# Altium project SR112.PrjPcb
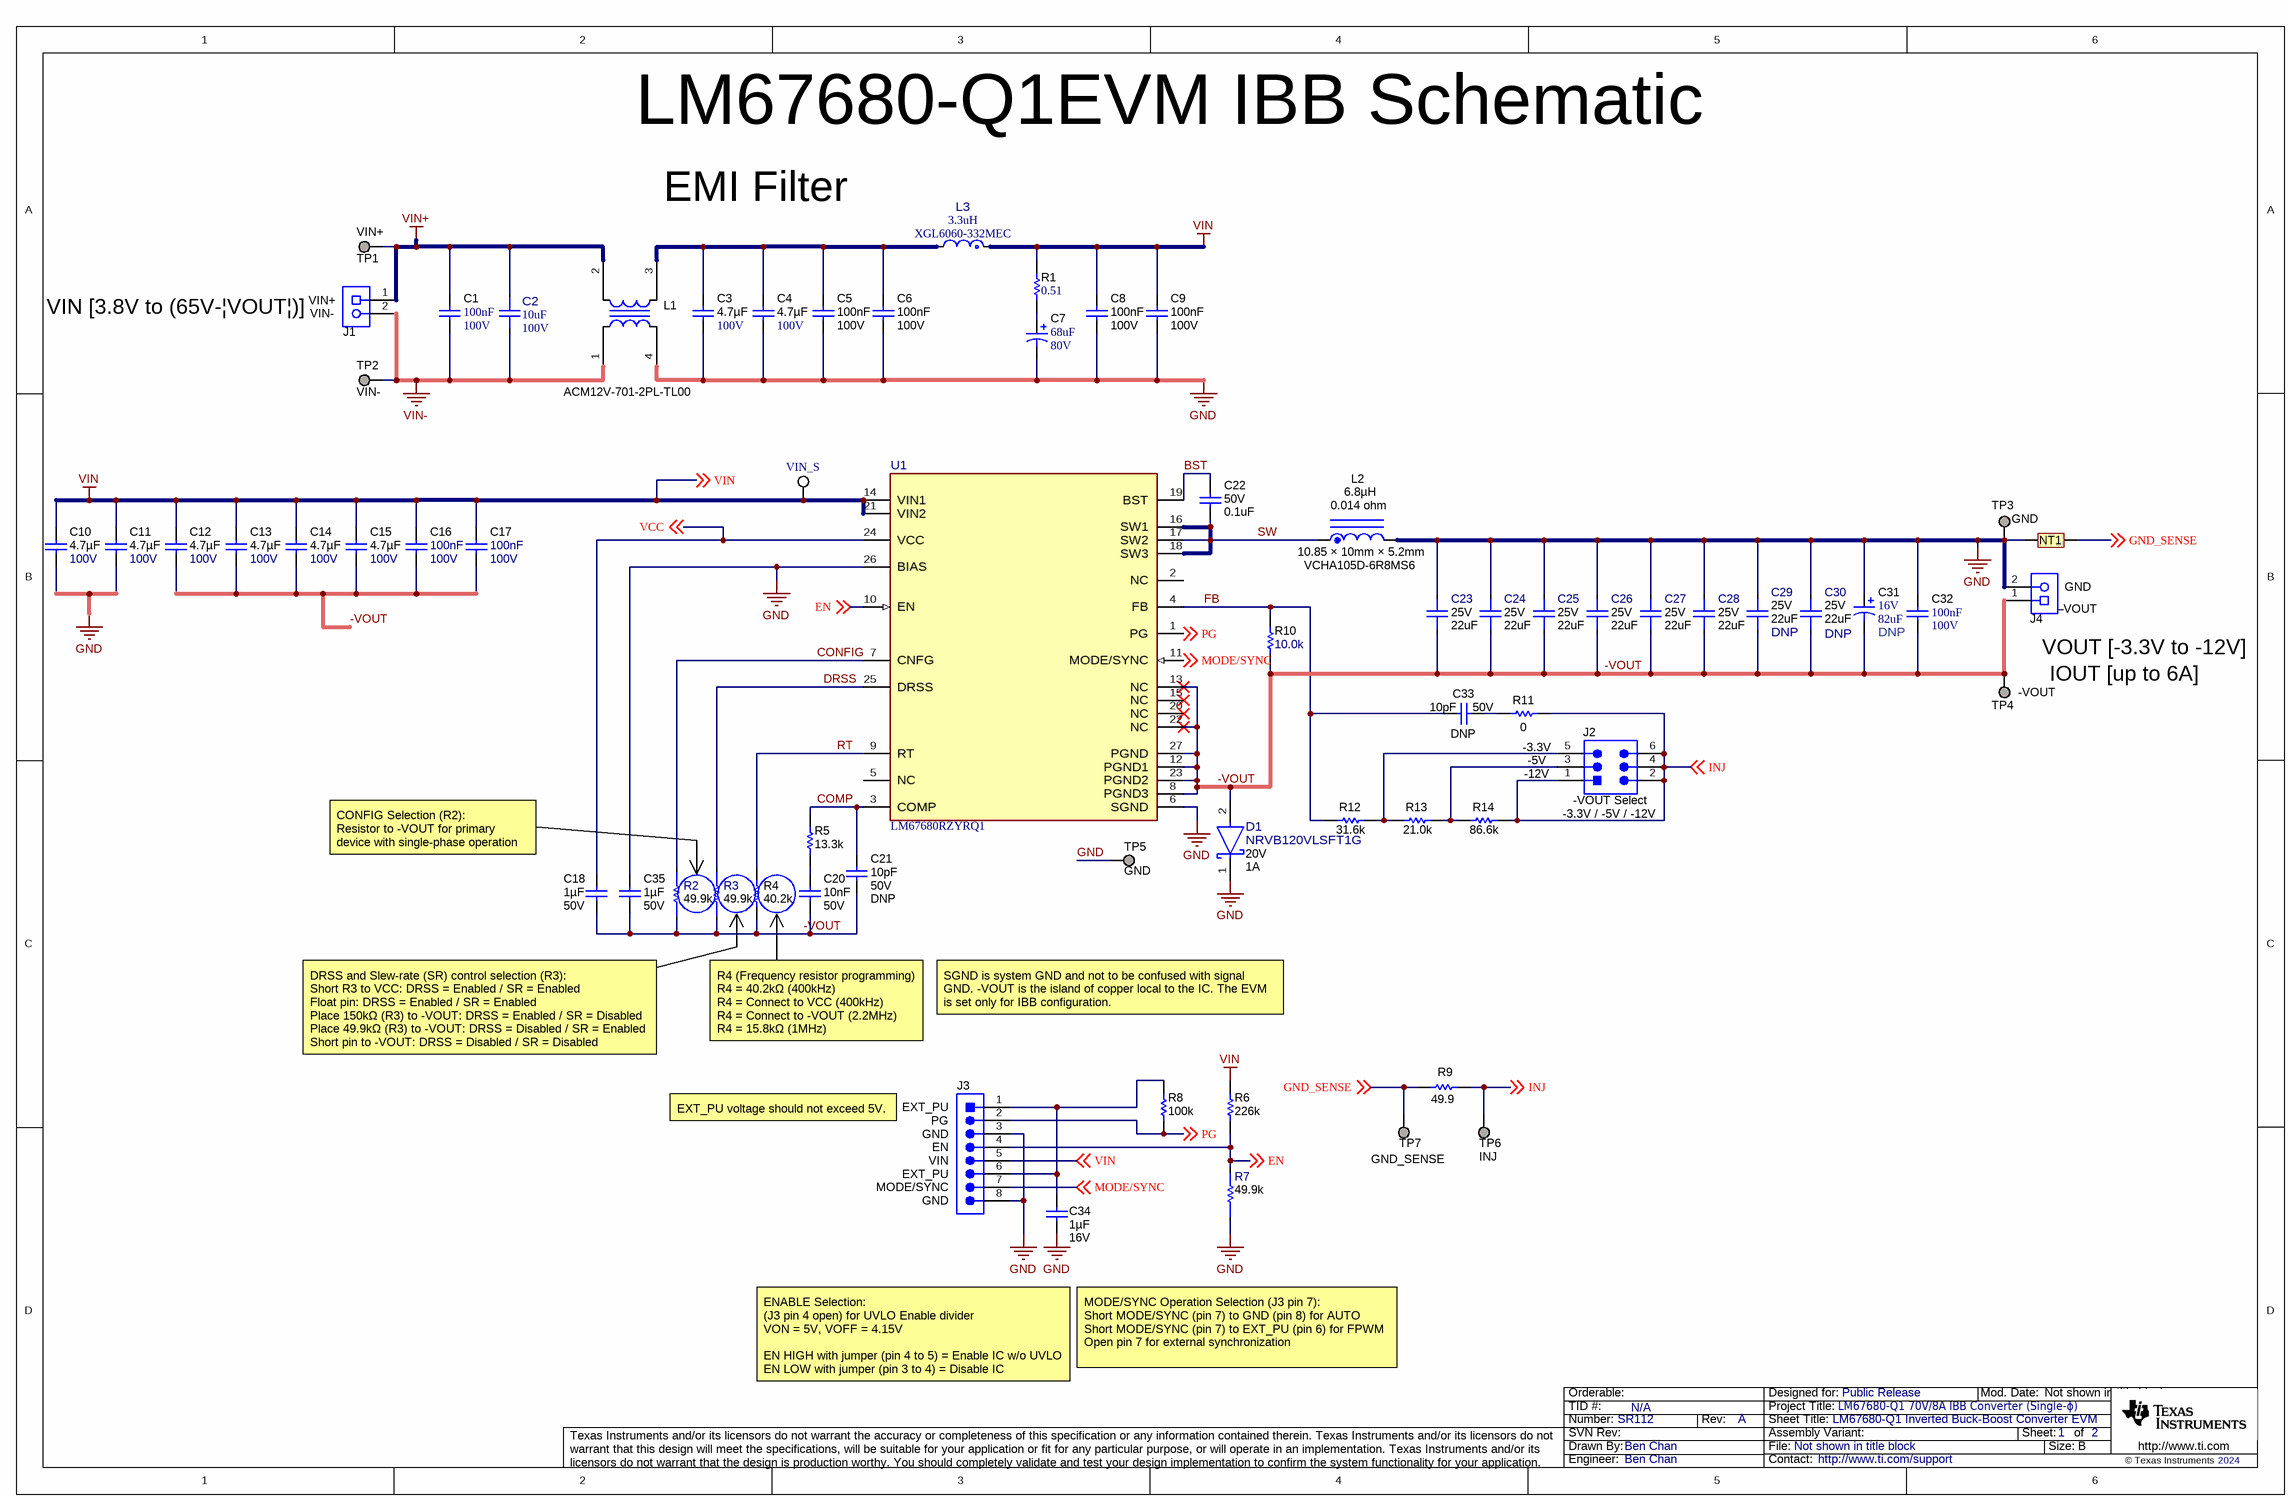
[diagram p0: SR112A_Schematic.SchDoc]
CopyrightYear: 2024; DrawnBy: Ben Chan; PCB_Layout: Ben Chan; PCB_Rev: A; PRJ_Customer: Public Release; PRJ_Engineer: Ben Chan; PRJ_Number: SR112; PRJ_Title: LM67680-Q1 70V/8A IBB Converter (Single-ϕ); SCH_Rev: A; TechSupport: http://www.ti.com/support; TID: N/A
2 sheets, 98 parts. Net scope: global (net labels, ports and power ports of the same name join across sheets).
Board file: SR112A.PcbDoc
Sheets:
  SR112A_Schematic.SchDoc
  SR112A_Hardware.SchDoc

## Sheet SR112A_Schematic.SchDoc: LM67680-Q1 Inverted Buck-Boost Converter EVM
size 431 x 279 mm; Date: Not shown in title block; ApprovedBy: Not shown in title block; CheckedBy: Not shown in title block; Author: Not shown in title block; CompanyName: Not shown in title block; Engineer: Not shown in title block; Organization: Not shown in title block; Address1: Not shown in title block; Address2: Not shown in title block; Address3: Not shown in title block; Address4: Not shown in title block; DocumentNumber: 1; Revision: Use project parameter SCH_Rev; SheetNumber: 1; SheetTotal: 2

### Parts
C1  Cap_F: 100nF  VDC_V: 100V  [0603S]
C2  ValueDisplayed: 10uF  VDC_V: 100V  [FP-CGA6P1X7R2A106K250AC_1210-MFG]  (hidden comment: CGA6P1X7R2A106K250AC)
C3  Value2: 100V  ValueDisplayed: 4.7µF  [1210_220L]  (hidden comment: GCM32DC72A475KE02L)
C4  Value2: 100V  ValueDisplayed: 4.7µF  [1210_220L]  (hidden comment: GCM32DC72A475KE02L)
C5  Cap_F: 100nF  VDC_V: 100V  [0805_HV]  (hidden comment: CGA4J2X7R2A104K125AA)
C6  Cap_F: 100nF  VDC_V: 100V  [0805_HV]  (hidden comment: CGA4J2X7R2A104K125AA)
C7  VDC_V: 80V  ValueDisplayed: 68uF  [SM_RADIAL_H13]  (hidden comment: EEV-FK1K680Q)
C8  Cap_F: 100nF  VDC_V: 100V  [0805_HV]  (hidden comment: CGA4J2X7R2A104K125AA)
C9  Cap_F: 100nF  VDC_V: 100V  [0805_HV]  (hidden comment: CGA4J2X7R2A104K125AA)
C10  Value2: 100V  ValueDisplayed: 4.7µF  [1210_220L]  (hidden comment: GCM32DC72A475KE02L)
C11  Value2: 100V  ValueDisplayed: 4.7µF  [1210_220L]  (hidden comment: GCM32DC72A475KE02L)
C12  Value2: 100V  ValueDisplayed: 4.7µF  [1210_220L]  (hidden comment: GCM32DC72A475KE02L)
C13  Value2: 100V  ValueDisplayed: 4.7µF  [1210_220L]  (hidden comment: GCM32DC72A475KE02L)
C14  Value2: 100V  ValueDisplayed: 4.7µF  [1210_220L]  (hidden comment: GCM32DC72A475KE02L)
C15  Value2: 100V  ValueDisplayed: 4.7µF  [1210_220L]  (hidden comment: GCM32DC72A475KE02L)
C16  Cap_F: 100nF  VDC_V: 100V  [0603S]  (hidden comment: CINHF1)
C17  Cap_F: 100nF  VDC_V: 100V  [0603S]  (hidden comment: CINHF2)
C18  VDC_V: 50V  ValueDisplayed: 1µF  [0603]  (hidden comment: CGA3E3X5R1H105M080AB)
C20  VDC_V: 50V  ValueDisplayed: 10nF  [0603]  (hidden comment: CGA3E2C0G1H103J080AA)
C21  DNP  VDC_V: 50V  ValueDisplayed: 10pF  [0603]
C22  VDC_V: 50V  ValueDisplayed: 0.1uF  [0402]  (hidden comment: CGA2B3X7R1H104K050BB)
C23  ValueDisplayed: 22uF  VDC_V: 25V  [FP-CGA6P3X7R1E226M250AB_1210-MFG]  (hidden comment: CGA6P3X7R1E226M250AB)
C24  ValueDisplayed: 22uF  VDC_V: 25V  [FP-CGA6P3X7R1E226M250AB_1210-MFG]  (hidden comment: CGA6P3X7R1E226M250AB)
C25  ValueDisplayed: 22uF  VDC_V: 25V  [FP-CGA6P3X7R1E226M250AB_1210-MFG]  (hidden comment: CGA6P3X7R1E226M250AB)
C26  ValueDisplayed: 22uF  VDC_V: 25V  [FP-CGA6P3X7R1E226M250AB_1210-MFG]  (hidden comment: CGA6P3X7R1E226M250AB)
C27  ValueDisplayed: 22uF  VDC_V: 25V  [FP-CGA6P3X7R1E226M250AB_1210-MFG]  (hidden comment: CGA6P3X7R1E226M250AB)
C28  ValueDisplayed: 22uF  VDC_V: 25V  [FP-CGA6P3X7R1E226M250AB_1210-MFG]  (hidden comment: CGA6P3X7R1E226M250AB)
C29  DNP  ValueDisplayed: 22uF  VDC_V: 25V  [FP-CGA6P3X7R1E226M250AB_1210-MFG]
C30  DNP  ValueDisplayed: 22uF  VDC_V: 25V  [FP-CGA6P3X7R1E226M250AB_1210-MFG]
C31  DNP  VDC_V: 16V  ValueDisplayed: 82uF  [WCAP-PSLP_630x580]
C32  Cap_F: 100nF  VDC_V: 100V  [0603S]  (hidden comment: CINHF1)
C33  DNP  VDC_V: 50V  ValueDisplayed: 10pF  [0603]
C34  Cap_F: 1µF  VDC_V: 16V  [0603]  (hidden comment: GCM188R71C105MA64D)
C35  VDC_V: 50V  ValueDisplayed: 1µF  [0603]  (hidden comment: CGA3E3X5R1H105M080AB)
D1  NRVB120VLSFT1G  Vf_V: 20V  Forward Current: 1A  [FP-NRVB120VLSFT1G_SOD-123-MFG]
J1  691 101 710 002  [Wurth_691101710002]  (value not drawn)
J2  (no value)  [TE_5-146254-3]
J3  5-146278-8  [TE_5-146278-8]  (value not drawn)
J4  691 101 710 002  [Wurth_691101710002]  (value not drawn)
L1  ACM12V-701-2PL-TL00  [TDK_ACM12V]
L2  VCHA105D-6R8MS6  PackageReference: 10.85 × 10mm × 5.2mm  Value1: 0.014 ohm  ValueDisplayed: 6.8µH  [VCHA105D]
L3  value 3.3uH  PartNumber: XGL6060-332MEC  [FP-XGL6060-332MEC_SMT_6MM51_6MM71-MFG]
NT1  Net-Tie  [Net-Tie_10mil]  (value not drawn)  (net tie, no BOM)
R1  ValueDisplayed: 0.51  [0603]  (hidden comment: ERJ-3RQFR51V)
R2  Res_ohm: 49.9k  [FP-CRCW060349K9FKEA_0603-MFG]  (hidden comment: CRCW060349K9FKEA)
R3  Res_ohm: 49.9k  [FP-CRCW060349K9FKEA_0603-MFG]  (hidden comment: CRCW060349K9FKEA)
R4  ValueDisplayed: 40.2k  [0603]  (hidden comment: CRCW060340K2FKEA)
R5  ValueDisplayed: 13.3k  [0603]  (hidden comment: CRCW060313K3FKEA)
R6  ValueDisplayed: 226k  [0603]  (hidden comment: CRCW0603226KFKEA)
R7  Res_ohm: 49.9k  [FP-CRCW060349K9FKEA_0603-MFG]  (hidden comment: CRCW060349K9FKEA)
R8  ValueDisplayed: 100k  [0603]  (hidden comment: CRCW0603100KFKEA)
R9  ValueDisplayed: 49.9  [0603]  (hidden comment: CRCW060349R9FKEA)
R10  ValueDisplayed: 10.0k  [0603]  (hidden comment: CRCW060310K0FKEA)
R11  ValueDisplayed: 0  [0603]  (hidden comment: RMCF0603ZT0R00)
R12  ValueDisplayed: 31.6k  [0603]  (hidden comment: CRCW060331K6FKEA)
R13  ValueDisplayed: 21.0k  [0603]  (hidden comment: CRCW060321K0FKEA)
R14  ValueDisplayed: 86.6k  [0603]  (hidden comment: CRCW060386K6FKEA)
TP1  VIN+  [Keystone_5019]
TP2  VIN-  [Keystone_5019]
TP3  GND  [Keystone_5019]
TP4  -VOUT  [Keystone_5019]
TP5  GND  [Keystone_5019]
TP6  INJ  [Keystone_5019]
TP7  GND_SENSE  [Keystone_5019]
U1  LM67680RZYRQ1  [RZY0026A-MFG]
VIN_S  5015  [Testpoint_Keystone_Miniature]  (value not drawn)

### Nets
GND: C3.2 C4.2 C5.2 C6.2 C7.2(-) C8.2 C9.2 C10.2 C11.2 C23.2 C24.2 C25.2 C26.2 C27.2 C28.2 C29.2 C30.2 C31.1(+) C32.1 C34.2 C35.1 D1.1(CATHODE) J3.3 J3.8 J4.2 L1.4 L2.2 NT1.1 R7.1 TP3.1 TP5.1 U1.6(SGND) U1.26(BIAS)
VIN: C8.1 C9.1 C10.1 C11.1 C12.1 C13.1 C14.1 C15.1 C16.1 C17.1 J3.5 L3.1 R1.2 R6.2 U1.14(VIN1) U1.21(VIN2) VIN_S.1 ; off-sheet VIN
VIN+: C1.1 C2.1 J1.1 L1.2 TP1.1
VIN-: C1.2 C2.2 J1.2 L1.1 TP2.1
-VOUT: C12.2 C13.2 C14.2 C15.2 C16.2 C17.2 C18.2 C20.2 C21.1 C23.1 C24.1 C25.1 C26.1 C27.1 C28.1 C29.1 C30.1 C31.2(-) C32.2 C35.2 D1.2(ANODE) J4.1 R2.1 R3.1 R4.1 R10.1 TP4.1 U1.8(PGND3) U1.12(PGND1) U1.13(NC) U1.22(NC) U1.23(PGND2) U1.27(PGND)
BST: C22.1 U1.19(BST)
COMP: C21.2 R5.2 U1.3(COMP)
CONFIG: R2.2 U1.7(CNFG)
DRSS: R3.2 U1.25(DRSS)
EN: J3.4 R6.1 R7.2 U1.10(EN) ; off-sheet EN
FB: C33.1 R10.2 R12.2 U1.4(FB)
GND_SENSE: NT1.2 R9.2 TP7.1 ; off-sheet GND_SENSE
INJ: J2.1 J2.2 J2.4 J2.6 R9.1 R11.2 R14.2 TP6.1 ; off-sheet INJ
MODE/SYNC: J3.7 U1.11(MODE/SYNC) ; off-sheet MODE/SYNC
PG: J3.2 R8.2 U1.1(PG) ; off-sheet PG
RT: R4.2 U1.9(RT)
SW: C22.2 L2.1 U1.16(SW1) U1.17(SW2) U1.18(SW3)
VCC: C18.1 U1.24(VCC) ; off-sheet VCC
NetC3_1: C3.1 C4.1 C5.1 C6.1 L1.3 L3.2
NetC7_1: C7.1(+) R1.1
NetC20_1: C20.1 R5.1
NetC33_2: C33.2 R11.1
NetC34_1: C34.1 J3.1 J3.6 R8.1
NetJ2_3: J2.3 R13.1 R14.1
NetJ2_5: J2.5 R12.1 R13.2

Not connected (* = marked no-connect by the designer): U1 2(NC) 5(NC) 15(NC)* 20(NC)*

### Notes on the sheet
- LM67680-Q1EVM IBB Schematic
- EMI Filter
- VIN [3.8V to (65V-¦VOUT¦)]
- (near J1) VIN+
- (near J1) VIN-
- GND
- (near J4) –VOUT
- VOUT [-3.3V to -12V]
- (near TP4) IOUT [up to 6A]
- -3.3V
- -5V
- -12V
- CONFIG Selection (R2):
  Resistor to -VOUT for primary device with single-phase operation
  Do not float if R2 is removed.
- (near J2) -VOUT Select
- (near J2) -3.3V / -5V / -12V
- DRSS and Slew-rate (SR) control selection (R3):
  Short R3 to VCC: DRSS = Enabled / SR = Enabled
  Float pin: DRSS = Enabled / SR = Enabled
  Place 150kΩ (R3) to -VOUT: DRSS = Enabled / SR = Disabled
  Place 49.9kΩ (R3) to -VOUT: DRSS = Disabled / SR = Enabled
  Short pin to -VOUT: DRSS = Disabled / SR = Disabled
- R4 (Frequency resistor programming)
  R4 = 40.2kΩ (400kHz)
  R4 = Connect to VCC (400kHz)
  R4 = Connect to -VOUT (2.2MHz)
  R4 = 15.8kΩ (1MHz)
- SGND is system GND and not to be confused with signal GND. -VOUT is the island of copper local to the IC. The EVM is set only for IBB configuration.
- EXT_PU voltage should not exceed 5V.
- (near J3) PG
- (near J3) EXT_PU
- (near J3) GND
- (near J3) EN
- (near J3) VIN
- (near J3) MODE/SYNC
- ENABLE Selection:
  (J3 pin 4 open) for UVLO Enable divider
  VON = 5V, VOFF = 4.15V
  EN HIGH with jumper (pin 4 to 5) = Enable IC w/o UVLO
  EN LOW with jumper (pin 3 to 4) = Disable IC
- MODE/SYNC Operation Selection (J3 pin 7):
  Short MODE/SYNC (pin 7) to GND (pin 8) for AUTO
  Short MODE/SYNC (pin 7) to EXT_PU (pin 6) for FPWM
  Open pin 7 for external synchronization

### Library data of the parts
C1 C16 C17 C32 = CMP-0064935-4: CAP, CERM, 0.1 uF, 100 V,+/- 10%, X7R, AEC-Q200 Grade 1, 0603; Manufacturer: MuRata; PartNumber: GCJ188R72A104KA01D; TaMin_C: -55°C; Polarized: N; SizeAreaWB_mm2: 4.68; Value1: Unknown; U/M: EA; Value: 0.1uF; TaMax_C: 125°C; SizeZ_mm: 1; SizeX_mm: 1.6; SizeY_mm: 0.8; Cap_Case: 0603; SizeArea_mm2: 1.28; AEC Qualified: Y; AEC Category: Q200
C2 = CMP-0125410-1: 10 µF ±10% 100V Ceramic Capacitor X7R 1210 (3225 Metric); Manufacturer: TDK; AEC Grade: Grade 1; AEC Qualified: Yes; Cap_F: 10µF; SizeZ_mm: 2.8mm; TempCo: 15%; Value: 10µF
C3 C4 C10-C15 = CMP-0082268-1: CAP, CERM, 4.7 µF, 100 V,+/- 10%, X7S, AEC-Q200 Grade 1, 1210; Manufacturer: MuRata; TaMin_C: -55°C; ESR_ohm: 1m; Polarized: N; SizeAreaWB_mm2: 14.7; Value1: 0.001 ohm; U/M: EA; Value: 4.7uF; TaMax_C: 125°C; SizeZ_mm: 2.2; SizeX_mm: 3.2; SizeY_mm: 2.5; Cap_Case: 1210; SizeArea_mm2: 8; AEC Qualified: Y; IRMS_A: 6A; AEC Grade: 1; AEC Category: Q200
C5 C6 C8 C9 = CMP-0007969-2: CAP, CERM, 0.1 uF, 100 V, +/- 10%, X7R, AEC-Q200 Grade 1, 0805; Manufacturer: TDK; TaMin_C: -55°C; ESR_ohm: 0.020726; Polarized: N; SizeAreaWB_mm2: 6.75; Value1: 0.020726 ohm; U/M: EA; Value: 0.1uF; TaMax_C: 125°C; SizeZ_mm: 1.45; SizeX_mm: 2; SizeY_mm: 1.25; Cap_Case: 0805; SizeArea_mm2: 2.5; AEC Qualified: Y; IRMS_A: 1.456A; AEC Grade: 1; AEC Category: Q200
C7 = CMP-0011220-2: CAP, AL, 68 uF, 80 V, +/- 20%, 0.32 ohm, AEC-Q200 Grade 2, SMD; Manufacturer: Panasonic; TaMin_C: -55°C; ESR_ohm: 0.32; Polarized: Y; SizeAreaWB_mm2: 263.5; U/M: EA; Value: 68uF; TaMax_C: 105°C; SizeZ_mm: 13.5; SizeX_mm: 15; Cap_Case: H13; SizeArea_mm2: 202.5; CompType: Capacitor; Cap_F: 68µF; IRMS_A: 500mA; AEC Grade: 2; AEC Category: Q200
C18 C35 = CMP-0083707-1: CAP, CERM, 1 µF, 50 V,+/- 20%, X5R, AEC-Q200 Grade 3, 0603; Manufacturer: TDK; SizeAreaWB_mm2: 4.68; SizeArea_mm2: 1.28; AEC Qualified: Y; AEC Category: Q200; Value: 1uF; TaMax_C: 85°C; SizeZ_mm: 1; AEC Grade: 3; Polarized: N; TaMin_C: -55°C; SizeY_mm: 0.8; U/M: EA; SizeX_mm: 1.6
C20 = CMP-0007070-4: CAP, CERM, 0.01 uF, 50 V, +/- 5%, C0G/NP0, AEC-Q200 Grade 1, 0603; Manufacturer: TDK; TaMin_C: -55°C; Polarized: N; SizeAreaWB_mm2: 4.68; Value1: Unknown; U/M: EA; Value: 0.01uF; TaMax_C: 125°C; SizeZ_mm: 1; SizeX_mm: 1.6; SizeY_mm: 0.8; SizeArea_mm2: 1.28; AEC Qualified: Y; AEC Category: Q200
C21 C33 = CMP-0007170-4: CAP, CERM, 10 pF, 50 V, +/- 5%, C0G/NP0, 0603; Manufacturer: MuRata; PartNumber: GRM1885C1H100JA01D; TaMin_C: -55°C; Polarized: N; SizeAreaWB_mm2: 4.68; Value1: Unknown; U/M: EA; Value: 10pF; TaMax_C: 125°C; SizeZ_mm: 1; SizeX_mm: 1.6; SizeY_mm: 0.8; SizeArea_mm2: 1.28; AEC Category: Q200
C22 = CMP-0006325-2: CAP, CERM, 0.1 uF, 50 V, +/- 10%, X7R, AEC-Q200 Grade 1, 0402; Manufacturer: TDK; TaMin_C: -55°C; ESR_ohm: 0.039064; Polarized: N; SizeAreaWB_mm2: 3; Value1: 0.039064 ohm; U/M: EA; Value: 0.1uF; TaMax_C: 125°C; SizeZ_mm: 0.6; SizeX_mm: 1; SizeY_mm: 0.5; AEC Qualified: Y; Cap_F: 100nF; IRMS_A: 8.14669dA; AEC Category: Q200
C23-C28 = CMP-0036912-1: Cap Ceramic 22uF 25V X7R 20% Pad SMD 1210 +125°C Automotive T/R; Manufacturer: TDK; AEC Grade: Grade 1; AEC Qualified: Yes; Cap_F: 22µF; SizeZ_mm: 2.8mm; TempCo: 15%; Tolerance_%: 0.2%; Value: 22µF
C29 C30 = CMP-0036912-1: Cap Ceramic 22uF 25V X7R 20% Pad SMD 1210 +125°C Automotive T/R; Manufacturer: TDK; PartNumber: CGA6P3X7R1E226M250AB; AEC Grade: Grade 1; AEC Qualified: Yes; Cap_F: 22µF; SizeZ_mm: 2.8mm; TempCo: 15%; Tolerance_%: 0.2%; Value: 22µF
C31 = CMP-0012165-3: CAP, Aluminum Polymer, 82 uF, 16 V, +/- 20%, 0.03 ohm, D6.3xL5.8mm SMD; Manufacturer: Wurth Elektronik; PartNumber: 875105344009; TaMin_C: -55°C; ESR_ohm: 30m; Polarized: Y; Value: 82uF; TaMax_C: 105°C; Cap_Case: 6.3x5.8mm; CompType: Capacitor; AEC Qualified: N; Cap_F: 82µF; IRMS_A: 2.2A; AEC Category: Q200
C34 = CMP-0007137-5: CAP, CERM, 1 uF, 16 V, +/- 20%, X7R, AEC-Q200 Grade 1, 0603; Manufacturer: MuRata; TaMin_C: -55°C; Polarized: N; SizeAreaWB_mm2: 4.68; Value1: Unknown; U/M: EA; Value: 1uF; TaMax_C: 125°C; SizeZ_mm: 1; SizeX_mm: 1.6; SizeY_mm: 0.8; SizeArea_mm2: 1.28; AEC Qualified: Y; AEC Category: Q200
D1 = CMP-0124232-1: Diode Schottky 20 V 1A Surface Mount SOD-123FL; Manufacturer: On Semi; AEC Qualified: No; SizeZ_mm: 0.98mm; TJmax_C: 125°C; Max Surge Forward Current: 45A; Peak Reverse Current: 0.6mA; Standoff Height: 0mm
J1 J4 = CMP-0054828-1: Terminal Block, 5 mm, 2x1, Tin, TH; Manufacturer: Wurth Elektronik; CNHeader: FALSE; Green_Lifecycle: Active; Green_REACh: Passed; CT: TRUE
J2 = CMP-0054953-2: Header, 100mil, 3x2, Tin, TH; Manufacturer: TE Connectivity; PartNumber: 5-146254-3; Green_REACh: Passed; Green_Lifecycle: Active
J3 = CMP-0054949-1: Header, 100mil, 8x1, Tin, TH; Manufacturer: TE Connectivity; CNHeader: TRUE; Green_Lifecycle: Active; Green_REACh: Passed; CT: FALSE
L1 = CMP-0084691-1: Coupled inductor,  ohm, AEC-Q200 Grade 1, SMD; Manufacturer: TDK; AEC Grade: 1; AEC Category: Q200; SizeZ_mm: 6; SizeX_mm: 12; AEC Qualified: Y; SizeAreaWB_mm2: 182; SizeArea_mm2: 132; SizeY_mm: 11
L2 = CMP-0082255-1: Inductor, Drum Core, Powdered Iron, 6.8 µH, 10.8 A, 0.014 ohm, AEC-Q200 Grade 0, SMD; Manufacturer: Cyntec; SizeAreaWB_mm2: 154.2; Irms: 10.8A @ 40C rise; SizeArea_mm2: 108.5; AEC Qualified: Y; AEC Category: Q200; Value: 6.8uH; SizeZ_mm: 5.4; Imax_A: 10.8A; AEC Grade: 0; SizeY_mm: 10; Isat: 11.4A @ 30% inductance drop; DCR_ohm: 0.014; SizeX_mm: 10.85
L3 = CMP-0093175-1: Shielded Power Inductors 3.3uH 20% tol, 6.5mOhm 16.6A; Manufacturer: Coilcraft; Shrouded: true; AEC Grade: Grade 1; TaMin_C: -40°C; Ind_H: 3.3µH; Test Frequency: 1MHz; DCR_ohm: 6.5m; Isat: 6.6A; Material: Composite; Self Resonant Frequency: 24MHz; SizeZ_mm: 6.1mm; AEC Qualified: Yes; TaMax_C: +125°C
NT1 = CMP-0078142-4: Single point connection between nets.
R1 = CMP-0022717-1: RES, 0.51, 1%, 0.1 W, AEC-Q200 Grade 1, 0603; Manufacturer: Panasonic; Power_W: 100mW; TempCo: 300 ppm/C; Value_Code: R510; U/M: EA; Value: 0.51; EIA_Code: E96; SizeX_mm: 1.6; SizeY_mm: 0.8; SizeZ_mm: 1; Value2: 0.1W; SizeArea_mm2: 1.28; AEC Qualified: Y; AEC Category: Q200
R2 R3 R7 = CMP-0089139-1: 49.9 kOhms ±1% 0.1W, 1/10W Chip Resistor 0603 (1608 Metric) Automotive AEC-Q200 Thick Film; Approved Alternate Part Number: 541-1.00HHCT-ND; Manufacturer: Vishay; Power_W: 100mW; VDC_V: 75V; TempCo: 100ppm/K; AEC Grade: Grade 0; SizeZ_mm: 0.5mm; AEC Qualified: Yes
R4 = CMP-0022410-4: RES, 40.2 k, 1%, 0.1 W, AEC-Q200 Grade 0, 0603; Manufacturer: Vishay-Dale; Power_W: 100mW; TempCo: 100 ppm/C; Value_Code: 40k2; Value: 40.2k; EIA_Code: E96; SizeX_mm: 1.6; SizeY_mm: 0.8; SizeZ_mm: 1; Value2: 0.1W; SizeArea_mm2: 1.28; AEC Qualified: Y; VDC_V: 75V; AEC Category: Q200; AEC Grade: 0
R5 = CMP-0022043-4: RES, 13.3 k, 1%, 0.1 W, AEC-Q200 Grade 0, 0603; Manufacturer: Vishay-Dale; Power_W: 100mW; TempCo: 100 ppm/C; Value_Code: 13k3; Value: 13.3k; EIA_Code: E96; SizeX_mm: 1.6; SizeY_mm: 0.8; SizeZ_mm: 1; Value2: 0.1W; SizeArea_mm2: 1.28; AEC Qualified: Y; VDC_V: 75V; AEC Category: Q200; AEC Grade: 0
R6 = CMP-0022218-4: RES, 226 k, 1%, 0.1 W, AEC-Q200 Grade 0, 0603; Manufacturer: Vishay-Dale; Power_W: 100mW; TempCo: 100 ppm/C; Value: 226k; EIA_Code: E96; SizeX_mm: 1.6; SizeY_mm: 0.8; SizeZ_mm: 1; Value2: 0.1W; SizeArea_mm2: 1.28; AEC Qualified: Y; VDC_V: 75V; AEC Category: Q200; AEC Grade: 0
R8 = CMP-0021990-4: RES, 100 k, 1%, 0.1 W, AEC-Q200 Grade 0, 0603; Manufacturer: Vishay-Dale; Power_W: 100mW; TempCo: 100 ppm/C; Value: 100k; EIA_Code: E96; SizeX_mm: 1.6; SizeY_mm: 0.8; SizeZ_mm: 1; Value2: 0.1W; SizeArea_mm2: 1.28; AEC Qualified: Y; VDC_V: 75V; AEC Category: Q200; AEC Grade: 0
R9 = CMP-0022448-4: RES, 49.9, 1%, 0.1 W, AEC-Q200 Grade 0, 0603; Manufacturer: Vishay-Dale; Power_W: 100mW; TempCo: 100 ppm/C; Value_Code: 49R9; Value: 49.9; EIA_Code: E96; SizeX_mm: 1.6; SizeY_mm: 0.8; SizeZ_mm: 1; Value2: 0.1W; SizeArea_mm2: 1.28; AEC Qualified: Y; VDC_V: 75V; AEC Category: Q200; AEC Grade: 0
R10 = CMP-0021998-4: RES, 10.0 k, 1%, 0.1 W, AEC-Q200 Grade 0, 0603; Manufacturer: Vishay-Dale; Power_W: 100mW; TempCo: 100 ppm/C; Value_Code: 10k0; Value: 10.0k; EIA_Code: E96; Res_ohm: 10k; SizeX_mm: 1.6; SizeY_mm: 0.8; SizeZ_mm: 1; Value2: 0.1W; SizeArea_mm2: 1.28; AEC Qualified: Y; VDC_V: 75V; AEC Category: Q200; AEC Grade: 0
R11 = CMP-0023343-3: RES, 0, 1%, 0.1 W, AEC-Q200 Grade 0, 0603; Manufacturer: Stackpole Electronics Inc; Power_W: 100mW; TempCo: ppm/C; U/M: EA; Value: 0; SizeX_mm: 1.6; SizeY_mm: 0.8; SizeZ_mm: 1; Value2: 0.1W; SizeArea_mm2: 1.28; AEC Qualified: Y; AEC Category: Q200
R12 = CMP-0022330-4: RES, 31.6 k, 1%, 0.1 W, AEC-Q200 Grade 0, 0603; Manufacturer: Vishay-Dale; Power_W: 100mW; TempCo: 100 ppm/C; Value_Code: 31k6; Value: 31.6k; EIA_Code: E96; SizeX_mm: 1.6; SizeY_mm: 0.8; SizeZ_mm: 1; Value2: 0.1W; SizeArea_mm2: 1.28; AEC Qualified: Y; VDC_V: 75V; AEC Category: Q200; AEC Grade: 0
R13 = CMP-0022212-4: RES, 21.0 k, 1%, 0.1 W, AEC-Q200 Grade 0, 0603; Manufacturer: Vishay-Dale; Power_W: 100mW; TempCo: 100 ppm/C; Value_Code: 21k0; Value: 21.0k; EIA_Code: E96; Res_ohm: 21k; SizeX_mm: 1.6; SizeY_mm: 0.8; SizeZ_mm: 1; Value2: 0.1W; SizeArea_mm2: 1.28; AEC Qualified: Y; VDC_V: 75V; AEC Category: Q200; AEC Grade: 0
R14 = CMP-0022628-4: RES, 86.6 k, 1%, 0.1 W, AEC-Q200 Grade 0, 0603; Manufacturer: Vishay-Dale; Power_W: 100mW; TempCo: 100 ppm/C; Value_Code: 86k6; Value: 86.6k; EIA_Code: E96; SizeY_mm: 0.8; SizeZ_mm: 1; Value2: 0.1W; SizeArea_mm2: 1.28; AEC Qualified: Y; VDC_V: 75V; AEC Category: Q200; SizeX_mm: 1.6; AEC Grade: 0
TP1-TP7 = CMP-0055162-1: Test Point, Miniature, SMT; Manufacturer: Keystone; PartNumber: 5019; CNHeader: FALSE; Green_Lifecycle: Active; Green_REACh: Passed; CT: TRUE
U1 = CMP-0127710-1: 65V, 8A Buck Converters Optimized for Inverting or Non-Inverting Outputs; Manufacturer: Texas Instruments; SizeZ_mm: 0.7mm; AEC Qualified: No; Min Supply Voltage: 3V; Negative Voltage Available: true; Nominal Supply Current: 42-56uA; Number Of Outputs: 1; Output Type: AdjustableProgrammable; Output Voltage: 0.8-60V; Standoff Height: 0mm; Switching Frequency: 300-2200kHz; Switching Topology: Buck,Buck-Boost; TJmax_C: +150°C
VIN_S = CMP-0055152-1: Test Point, Miniature, SMT; Manufacturer: Keystone; CNHeader: FALSE; Green_Lifecycle: Active; Green_REACh: Passed; CT: TRUE

## Sheet SR112A_Hardware.SchDoc: LM67680-Q1 IBB EVM Hardware
size 431 x 279 mm; Date: Not shown in title block; ApprovedBy: Not shown in title block; CheckedBy: Not shown in title block; Author: Not shown in title block; CompanyName: Not shown in title block; Engineer: Not shown in title block; Organization: Not shown in title block; Address1: Not shown in title block; Address2: Not shown in title block; Address3: Not shown in title block; Address4: Not shown in title block; DocumentNumber: 2; Revision: Use project parameter SCH_Rev; SheetNumber: 2; SheetTotal: 2; PageSetup: Record=PageOptions¦CenterHorizontal=True¦CenterVertical=True¦PrintScale=1.00¦XCorrection=1.00¦YCorrection=1.00¦PrintKind=0¦BorderSize=5000000¦LeftOffset=0¦BottomOffset=0¦Orientation=2¦PaperLength=1000¦PaperWidth=1000¦Scale=100¦PaperSource=15¦PrintQuality=600¦MediaType=1¦DitherType=10¦PaperKind=Letter¦PrintScaleMode=1
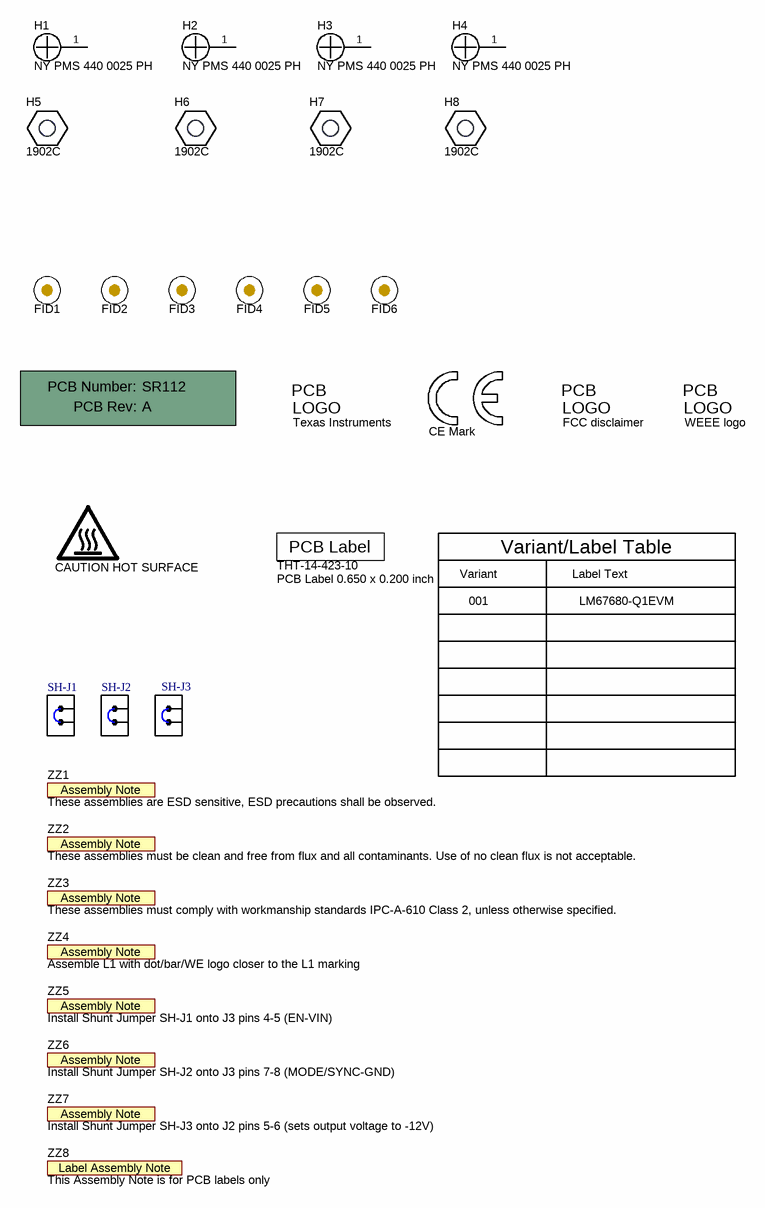
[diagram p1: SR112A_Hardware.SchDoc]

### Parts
!PCB1  Printed Circuit Board  (value not drawn)  (mechanical)
FID1  Fiducial  [Fiducial10-20]  (value not drawn)
FID2  Fiducial  [Fiducial10-20]  (value not drawn)
FID3  Fiducial  [Fiducial10-20]  (value not drawn)
FID4  Fiducial  [Fiducial10-20]  (value not drawn)
FID5  Fiducial  [Fiducial10-20]  (value not drawn)
FID6  Fiducial  [Fiducial10-20]  (value not drawn)
H1  NY PMS 440 0025 PH  [NY PMS 440 0025 PH]
H2  NY PMS 440 0025 PH  [NY PMS 440 0025 PH]
H3  NY PMS 440 0025 PH  [NY PMS 440 0025 PH]
H4  NY PMS 440 0025 PH  [NY PMS 440 0025 PH]
H5  1902C  [Keystone_1902C]
H6  1902C  [Keystone_1902C]
H7  1902C  [Keystone_1902C]
H8  1902C  [Keystone_1902C]
LBL1  THT-14-423-10  PackageReference: PCB Label 0.650 x 0.200 inch  [Label_650x200]
Logo1  CE Mark  [CE_Mark_5mm]  (no BOM)
Logo2  Texas Instruments  [TI_Stacked_Overlay_Small]  (no BOM)
Logo3  FCC disclaimer  [FCC_disclaimer]  (no BOM)
Logo4  WEEE logo  [WEEE_Minimum]  (no BOM)
LOGO5  CAUTION HOT SURFACE  [IEC_HotSurface_Small]  (no BOM)
SH-J1  SNT-100-BK-G  [SNT-100-BK-G]  (value not drawn)
SH-J2  SNT-100-BK-G  [SNT-100-BK-G]  (value not drawn)
SH-J3  SNT-100-BK-G  [SNT-100-BK-G]  (value not drawn)
ZZ1  These assemblies are ESD sensitive, ESD precautions shall be observed.  [AssemblyNote]  (no BOM)
ZZ2  These assemblies must be clean and free from flux and all contaminants. Use of no clean flux is not acceptable.  [AssemblyNote]  (no BOM)
ZZ3  These assemblies must comply with workmanship standards IPC-A-610 Class 2, unless otherwise specified.  [AssemblyNote]  (no BOM)
ZZ4  Assemble L1 with dot/bar/WE logo closer to the L1 marking  [AssemblyNote]  (no BOM)
ZZ5  Install Shunt Jumper SH-J1 onto J3 pins 4-5 (EN-VIN)  [AssemblyNote]  (no BOM)
ZZ6  Install Shunt Jumper SH-J2 onto J3 pins 7-8 (MODE/SYNC-GND)  [AssemblyNote]  (no BOM)
ZZ7  Install Shunt Jumper SH-J3 onto J2 pins 5-6 (sets output voltage to -12V)  [AssemblyNote]  (no BOM)
ZZ8  This Assembly Note is for PCB labels only  [AssemblyNoteLabel]  (no BOM)

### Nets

Not connected (* = marked no-connect by the designer): H1 1; H2 1; H3 1; H4 1

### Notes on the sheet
- Variant
- Variant/Label Table
- Label Text
- 001
- LM67680-Q1EVM

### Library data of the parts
!PCB1 = CMP-0003618-2: Manufacturer: Any; PartNumber: SR112
FID1-FID6 = CMP-0077181-1: Fiducial mark.  There is nothing to buy or mount.
H1-H4 = CMP-0003617-1: Machine Screw, Round, #4-40 x 1/4, Nylon, Philips panhead; Manufacturer: B&F Fastener Supply; CompType: Hardware
H5-H8 = CMP-0003610-1: Standoff, Hex, 0.5"L #4-40 Nylon; Manufacturer: Keystone; CompType: Hardware
LBL1 = CMP-0003625-1: Thermal Transfer Printable Labels, 0.650" W x 0.200" H - 10,000 per roll; Manufacturer: Brady; Note: Size: 0.65" x 0.20 "
Logo1 = CMP-0074844-1: SymbolCreator: a0412235
Logo2 = CMP-0074838-1: Texas Instrument Corporate Signature; SymbolCreator: a0412235; Lib Reference: TI_Logo; Library Reference: Logo
Logo3 = CMP-0074847-1: FCC_disclaimer; Library Reference: Logo
Logo4 = CMP-0074769-1
LOGO5 = CMP-0074837-1: IEC 61010-1 Hot Surface Warning; Library Reference: IEC_HotSurface; SymbolCreator: a0412235
SH-J1-SH-J3 = CMP-0003623-3: Shunt, 100mil, Gold plated, Black; Alternate PartNumber: 969102-0000-DA; Manufacturer: Samtec; Alternate Manufacturer: 3M; Value: 1x2; Note: You can "mate" this to a header by matching the designator.  i.e. use SH-J3 for header J3
ZZ1 = CMP-0077236-1
ZZ2 = CMP-0077237-1
ZZ3 = CMP-0077238-1
ZZ4 = CMP-0077238-1: These assemblies must comply with workmanship standards IPC-A-610 Class 2, unless otherwise specified.
ZZ5 = CMP-0077238-1: Install Shunt Jumper SH-J1 onto J3 pins 2-3 BIAS-VOUT)
ZZ6 = CMP-0077238-1: Install Shunt Jumper SH-J2 onto J3 pins 11-12 (EN-VIN)
ZZ7 = CMP-0077238-1: Install Shunt Jumper SH-J4 onto J3 pin 8 (SYNC))
ZZ8 = CMP-0003616-3

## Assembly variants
001: not fitted C12 C13 C14 C15 C21 C29 C30 C31 C33 FID1 FID2 FID3 FID4 FID5 FID6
